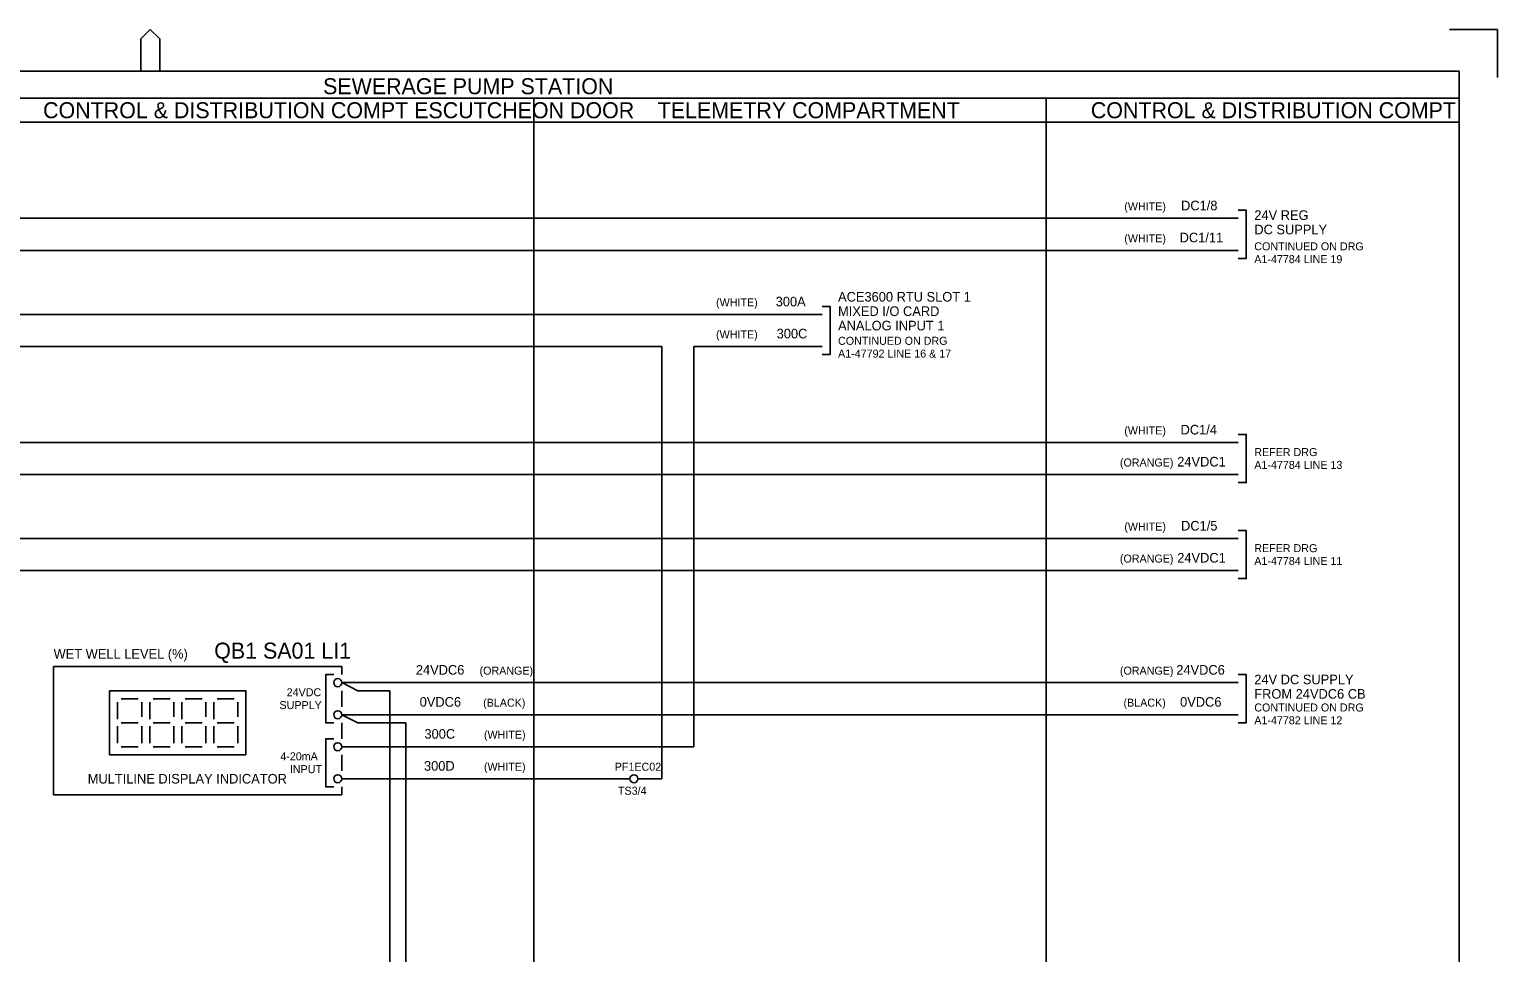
# Model space of a CAD drawing. Extents: x 0 to 841, y 0 to 594.
# Drawn here: x 382.4 to 841, y 305.7 to 594 of the extents above; entities that cross this region are included whole.
import ezdxf

# ---------------------------------------------------------------- set-up
doc = ezdxf.new("R2010")
doc.units = 0
for name, color, linetype in [('A1BORDER', 7, 'Continuous'), ('BASE', 7, 'Continuous'), ('Level 1', 7, 'Continuous'), ('Level 10', 7, 'Continuous'), ('Level 2', 7, 'Continuous')]:
    doc.layers.add(name, color=color, linetype=linetype)

msp = doc.modelspace()

# ---------------------------------------------------------------- linework, layer by layer
at = {"layer": 'A1BORDER'}
for p, q in [((417.19, 591), (420.19, 594)), ((423.19, 591), (420.19, 594)), ((826, 594), (841, 594)), ((841, 579), (841, 594)), ((417.19, 581), (417.19, 591)), ((423.19, 581), (423.19, 591)), ((28, 581), (829, 581)), ((829, 581), (829, 15))]:
    msp.add_line(p, q, dxfattribs=at)
at = {"layer": 'BASE'}
for p, q in [((317.5, 535), (760, 535)), ((317.5, 525), (760, 525)), ((317.5, 505), (630, 505)), ((317.5, 495), (580, 495))]:
    msp.add_line(p, q, dxfattribs=at)
at = {"layer": 'Level 1'}
for p, q in [((120, 572.5), (829, 572.5)), ((540, 57), (540, 572.5)), ((700, 69), (700, 572.5)), ((120, 565), (829, 565)), ((580, 495), (580, 360)), ((630, 495), (590, 495)), ((590, 495), (590, 370)), ((760, 465), (317.5, 465)), ((760, 455), (317.5, 455)), ((760, 435), (317.5, 435)), ((760, 425), (317.5, 425)), ((760, 390), (480, 390)), ((480, 390), (485, 387.5)), ((485, 387.5), (495, 387.5)), ((495, 387.5), (495, 270)), ((480, 380), (760, 380)), ((480, 380), (485, 377.5)), ((485, 377.5), (500, 377.5)), ((500, 377.5), (500, 260)), ((480, 370), (590, 370)), ((570, 360), (480, 360)), ((570, 360), (570, 360)), ((580, 360), (572.5, 360)), ((572.5, 360), (572.5, 360))]:
    msp.add_line(p, q, dxfattribs=at)
for points in [[(760, 522.5), (762.5, 522.5), (762.5, 537.5), (760, 537.5)], [(630, 492.5), (632.5, 492.5), (632.5, 507.5), (630, 507.5)], [(760, 452.5), (762.5, 452.5), (762.5, 467.5), (760, 467.5)], [(760, 422.5), (762.5, 422.5), (762.5, 437.5), (760, 437.5)], [(477.5, 392.5), (475, 392.5), (475, 377.5), (477.5, 377.5)], [(760, 377.5), (762.5, 377.5), (762.5, 392.5), (760, 392.5)], [(477.5, 372.5), (475, 372.5), (475, 357.5), (477.5, 357.5)]]:
    msp.add_lwpolyline(points, dxfattribs=at)
msp.add_lwpolyline([(407.5, 387.5), (450, 387.5), (450, 367.5), (407.5, 367.5)], close=True, dxfattribs=at)
at = {"layer": 'Level 10'}
for centre in [(478.75, 390), (478.75, 380), (478.75, 370), (478.75, 360), (571.25, 360)]:
    msp.add_circle(centre, 1.25, dxfattribs=at)
at = {"layer": 'Level 2'}
for p, q in [((410, 383.88), (410, 378.63)), ((411.13, 385), (416.37, 385)), ((417.5, 383.88), (417.5, 379.38)), ((420, 383.88), (420, 378.63)), ((421.13, 385), (426.37, 385)), ((427.5, 383.88), (427.5, 379.38)), ((430, 383.88), (430, 378.63)), ((431.13, 385), (436.37, 385)), ((437.5, 383.88), (437.5, 379.38)), ((440, 383.88), (440, 378.63)), ((441.13, 385), (446.37, 385)), ((447.5, 383.88), (447.5, 379.38)), ((410, 376.38), (410, 371.13)), ((411.13, 377.5), (416.37, 377.5)), ((417.5, 376.38), (417.5, 371.13)), ((420, 376.38), (420, 371.13)), ((421.13, 377.5), (426.37, 377.5)), ((427.5, 376.38), (427.5, 371.13)), ((430, 376.38), (430, 371.13)), ((431.13, 377.5), (436.37, 377.5)), ((437.5, 376.38), (437.5, 371.13)), ((440, 376.38), (440, 371.13)), ((441.13, 377.5), (446.37, 377.5)), ((447.5, 376.38), (447.5, 371.13)), ((411.13, 370), (416.37, 370)), ((421.13, 370), (426.37, 370)), ((431.13, 370), (436.37, 370)), ((441.13, 370), (446.37, 370))]:
    msp.add_line(p, q, dxfattribs=at)
for points in [[(480, 392.5), (480, 395), (390, 395), (390, 355)], [(480, 382.5), (480, 387.5)], [(480, 372.5), (480, 377.5)], [(480, 362.5), (480, 367.5)], [(390, 355), (480, 355), (480, 357.5)]]:
    msp.add_lwpolyline(points, dxfattribs=at)

# ---------------------------------------------------------------- texts
at = {"layer": 'Level 1'}
for s, height, p in [('SEWERAGE PUMP STATION', 5, (474.16, 573.75)), ('CONTROL & DISTRIBUTION COMPT ESCUTCHEON DOOR', 5, (386.71, 566.25)), ('TELEMETRY COMPARTMENT', 5, (578.66, 566.25)), ('CONTROL & DISTRIBUTION COMPT', 5, (713.95, 566.25)), ('(WHITE)', 2.5, (724.4, 537.5)), ('DC1/8', 3, (742.12, 537.5)), ('24V REG', 3, (765, 534.5)), ('DC SUPPLY', 3, (765, 530)), ('(WHITE)', 2.5, (724.4, 527.5)), ('DC1/11', 3, (741.67, 527.5)), ('CONTINUED ON DRG', 2.5, (765, 525)), ('A1-47784 LINE 19', 2.5, (765, 521)), ('(WHITE)', 2.5, (596.9, 507.5)), ('300A', 3, (615.52, 507.5)), ('ACE3600 RTU SLOT 1', 3, (635, 509)), ('MIXED I/O CARD', 3, (635, 504.5)), ('(WHITE)', 2.5, (596.9, 497.5)), ('300C', 3, (615.82, 497.5)), ('ANALOG INPUT 1', 3, (635, 500)), ('CONTINUED ON DRG', 2.5, (635, 495.5)), ('A1-47792 LINE 16 & 17', 2.5, (635, 491.5)), ('(WHITE)', 2.5, (724.4, 467.5)), ('DC1/4', 3, (741.97, 467.5)), ('REFER DRG', 2.5, (765, 460.75)), ('(ORANGE)', 2.5, (723.03, 457.5)), ('24VDC1', 3, (740.93, 457.5)), ('A1-47784 LINE 13', 2.5, (765, 456.75)), ('DC1/5', 3, (742.12, 437.5)), ('(WHITE)', 2.5, (724.4, 437.5)), ('REFER DRG', 2.5, (765, 430.75)), ('(ORANGE)', 2.5, (723.03, 427.5)), ('24VDC1', 3, (740.93, 427.5)), ('A1-47784 LINE 11', 2.5, (765, 426.75)), ('WET WELL LEVEL (%)', 3, (390, 397.5)), ('QB1 SA01 LI1', 5, (440.16, 397.5)), ('24VDC6', 3, (503.13, 392.5)), ('(ORANGE)', 2.5, (523.03, 392.5)), ('(ORANGE)', 2.5, (723.03, 392.5)), ('24VDC6', 3, (740.63, 392.5)), ('24V DC SUPPLY', 3, (765, 389.5)), ('24VDC', 2.5, (462.79, 385.75)), ('0VDC6', 3, (504.32, 382.5)), ('0VDC6', 3, (741.82, 382.5)), ('FROM 24VDC6 CB', 3, (765, 385)), ('SUPPLY', 2.5, (460.55, 381.75)), ('(BLACK)', 2.5, (524.15, 382.5)), ('(BLACK)', 2.5, (724.15, 382.5)), ('CONTINUED ON DRG', 2.5, (765, 381)), ('A1-47782 LINE 12', 2.5, (765, 377)), ('300C', 3, (505.82, 372.5)), ('(WHITE)', 2.5, (524.4, 372.5)), ('4-20mA', 2.5, (460.8, 365.75)), ('INPUT', 2.5, (463.78, 361.75)), ('300D', 3, (505.67, 362.5)), ('(WHITE)', 2.5, (524.4, 362.5)), ('PF1EC02', 2.5, (565.27, 362.5)), ('TS3/4', 2.5, (566.27, 355))]:
    msp.add_text(s, height=height, dxfattribs=at).set_placement(p)
at = {"layer": 'Level 2'}
msp.add_text('MULTILINE DISPLAY INDICATOR', height=3, dxfattribs=at).set_placement((400.66, 358.5))

doc.saveas('drawing.dxf')
